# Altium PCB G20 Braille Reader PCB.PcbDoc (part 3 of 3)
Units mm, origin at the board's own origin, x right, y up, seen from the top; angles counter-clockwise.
Board outline 160.1 x 170.2 mm, 2 copper layers (Top Layer, Bottom Layer); 206 components, 272 nets, 975 pads, 345 vias.
Unrouted connection lines stored in the file: 1.
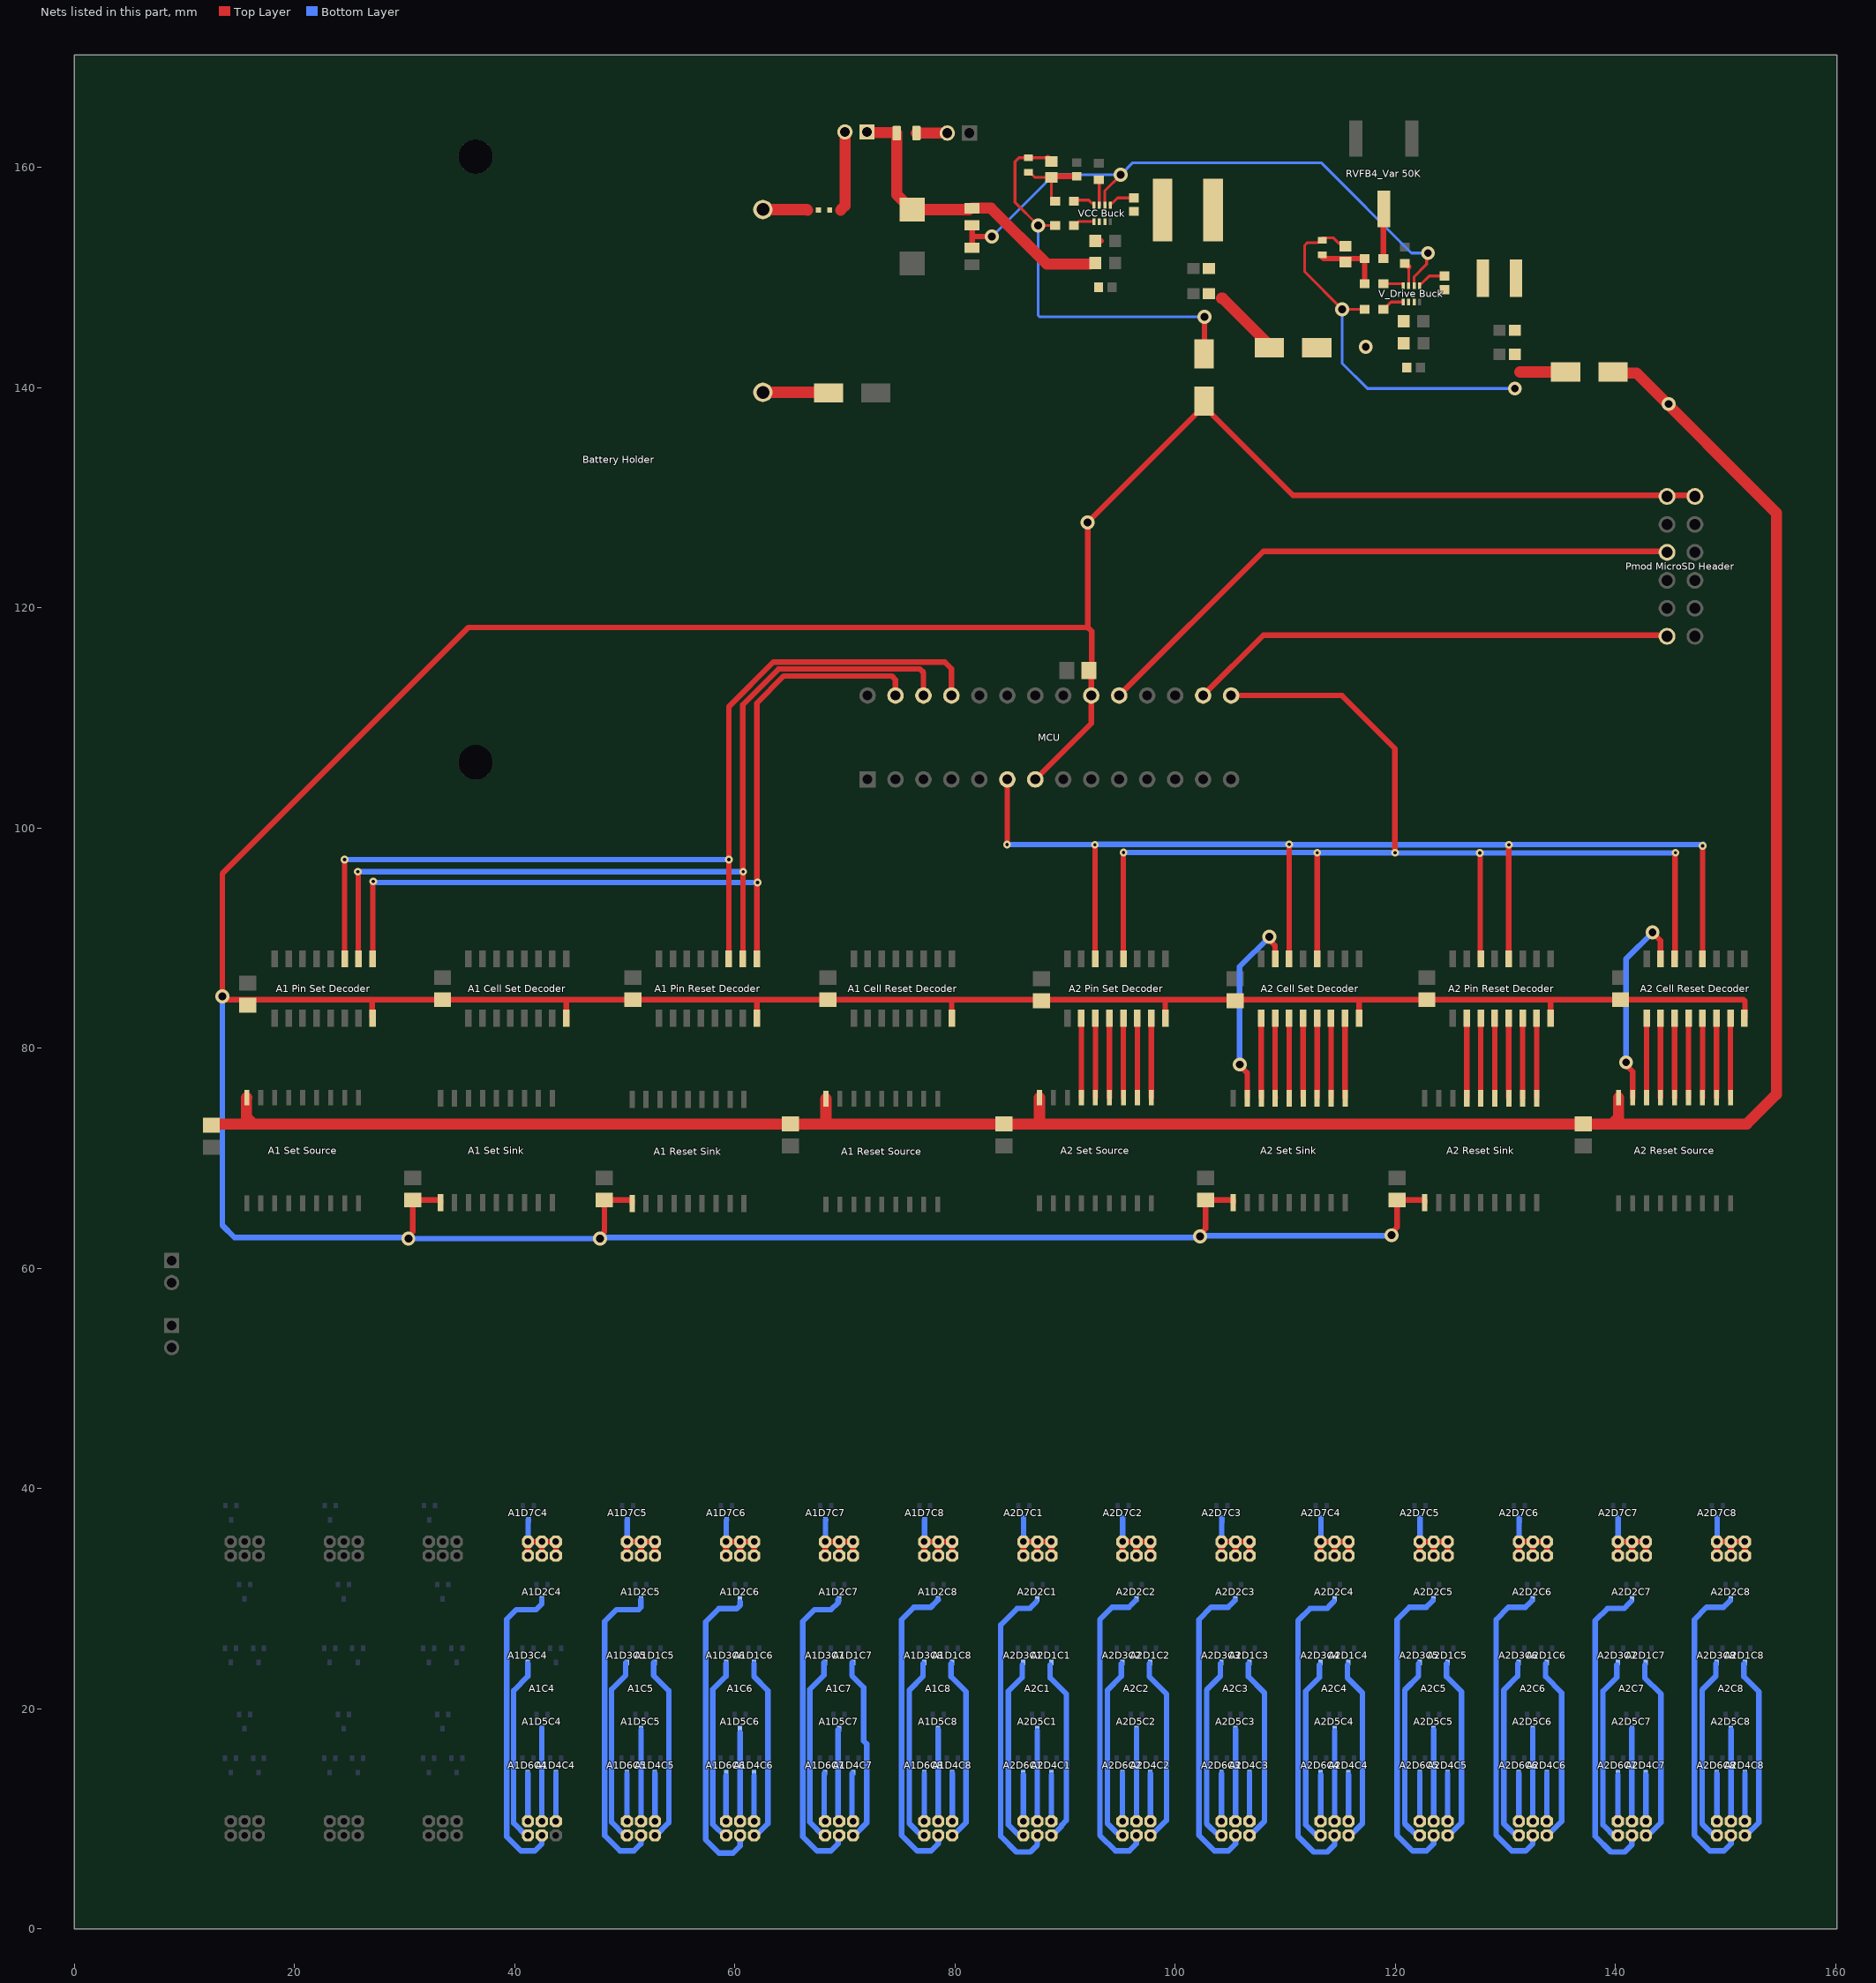
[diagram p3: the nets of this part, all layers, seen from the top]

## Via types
v1: diameter 0.7, hole 0.3, Top Layer to Bottom Layer, 308 vias
v2: diameter 1.27, hole 0.711, Top Layer to Bottom Layer, 37 vias

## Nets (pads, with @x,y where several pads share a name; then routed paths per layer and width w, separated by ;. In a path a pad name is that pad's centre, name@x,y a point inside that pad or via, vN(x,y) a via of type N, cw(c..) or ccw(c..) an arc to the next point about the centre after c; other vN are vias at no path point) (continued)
NetA1C4_P$2: A1C4.P$2 A1C4.P$4 A1C4.P$6 A1C4.P$8 A1C4.P$10 A1C4.P$12 A1D7C4.3 | length 8.4
  Top Layer w0.5: A1C4.P$8@41.2,33.907 A1C4.P$2@41.2,35.177 A1C4.P$4@42.47,35.177 ; A1C4.P$10@42.47,33.907 A1C4.P$4@42.47,35.177 ; A1C4.P$12@43.74,33.907 A1C4.P$6@43.74,35.177 A1C4.P$4@42.47,35.177
  Bottom Layer w0.5: A1C4.P$2@41.2,35.177 41.223,35.2 41.223,37.137 A1D7C4.3@41.246,37.16
NetA1C4_P$3: A1C4.P$3 A1D2C4.3 | length 28.6
  Bottom Layer w0.5: A1D2C4.3@42.467,29.906 42.457,29.896 42.457,29.516 41.946,29.005 40.146,29.005 39.273,28.132 39.273,8.386 40.56,7.099 41.83,7.099 42.47,7.739 A1C4.P$3@42.47,8.407
NetA1C4_P$5: A1C4.P$5 A1D3C4.3 | length 16.7
  Bottom Layer w0.5: A1C4.P$5@41.1,8.407 39.9,9.607 39.9,21.659 41.195,22.954 A1D3C4.3@41.195,24.097
NetA1C4_P$7: A1C4.P$7 A1D4C4.3 | length 4.4
  Bottom Layer w0.5: A1C4.P$7@43.742,9.689 A1D4C4.3@43.742,14.104
NetA1C4_P$9: A1C4.P$9 A1D5C4.3 | length 8.4
  Bottom Layer w0.5: A1C4.P$9@42.47,9.777 A1D5C4.3@42.47,18.192
NetA1C4_P$11: A1C4.P$11 A1D6C4.3 | length 4.4
  Bottom Layer w0.5: A1C4.P$11@41.202,9.689 A1D6C4.3@41.202,14.104
NetA1C5_P$1: A1C5.P$1 A1D1C5.3 | length 16.8
  Bottom Layer w0.5: A1D1C5.3@52.624,24.198 52.624,23.017 54,21.641 54,9.667 52.84,8.507 A1C5.P$1@52.74,8.507
NetA1C5_P$2: A1C5.P$2 A1C5.P$4 A1C5.P$6 A1C5.P$8 A1C5.P$10 A1C5.P$12 A1D7C5.3 | length 8.4
  Top Layer w0.5: A1C5.P$8@50.2,33.907 A1C5.P$2@50.2,35.177 A1C5.P$4@51.47,35.177 ; A1C5.P$10@51.47,33.907 A1C5.P$4@51.47,35.177 ; A1C5.P$12@52.74,33.907 A1C5.P$6@52.74,35.177 A1C5.P$4@51.47,35.177
  Bottom Layer w0.5: A1C5.P$2@50.2,35.177 50.223,35.2 50.223,37.137 A1D7C5.3@50.246,37.16
NetA1C5_P$3: A1C5.P$3 A1D2C5.3 | length 28.8
  Bottom Layer w0.5: A1D2C5.3@51.467,29.906 51.467,29.209 51.263,29.005 49.246,29.005 48.173,27.932 48.173,8.486 49.56,7.099 50.83,7.099 51.47,7.739 A1C5.P$3@51.47,8.407
NetA1C5_P$5: A1C5.P$5 A1D3C5.3 | length 16.7
  Bottom Layer w0.5: A1C5.P$5@49.989,8.508 48.8,9.698 48.8,21.771 50.084,23.055 A1D3C5.3@50.084,24.198
NetA1C5_P$7: A1C5.P$7 A1D4C5.3 | length 4.4
  Bottom Layer w0.5: A1C5.P$7@52.742,9.689 A1D4C5.3@52.742,14.104
NetA1C5_P$9: A1C5.P$9 A1D5C5.3 | length 8.4
  Bottom Layer w0.5: A1C5.P$9@51.472,9.689 A1D5C5.3@51.472,18.104
NetA1C5_P$11: A1C5.P$11 A1D6C5.3 | length 4.4
  Bottom Layer w0.5: A1C5.P$11@50.202,9.689 A1D6C5.3@50.202,14.104
NetA1C6_P$1: A1C6.P$1 A1D1C6.3 | length 16.7
  Bottom Layer w0.5: A1D1C6.3@61.735,24.097 61.735,22.916 63.007,21.644 63.007,9.584 ; A1C6.P$1@61.84,8.407 63.005,9.572
NetA1C6_P$2: A1C6.P$2 A1C6.P$4 A1C6.P$6 A1C6.P$8 A1C6.P$10 A1C6.P$12 A1D7C6.3 | length 8.4
  Top Layer w0.5: A1C6.P$8@59.2,33.907 A1C6.P$2@59.2,35.177 A1C6.P$4@60.47,35.177 ; A1C6.P$10@60.47,33.907 A1C6.P$4@60.47,35.177 ; A1C6.P$12@61.74,33.907 A1C6.P$6@61.74,35.177 A1C6.P$4@60.47,35.177
  Bottom Layer w0.5: A1C6.P$2@59.2,35.177 59.223,35.2 59.223,37.137 A1D7C6.3@59.246,37.16
NetA1C6_P$3: A1C6.P$3 A1D2C6.3 | length 28.4
  Bottom Layer w0.5: 60.467,29.706 60.467,29.393 60.174,29.1 58.541,29.1 57.346,27.905 57.346,8.113 58.56,6.899 59.83,6.899 60.47,7.539 A1C6.P$3@60.47,8.207
NetA1C6_P$5: A1C6.P$5 A1D3C6.3 | length 16.6
  Bottom Layer w0.5: A1C6.P$5@59.1,8.407 58,9.507 58,21.759 59.195,22.954 A1D3C6.3@59.195,24.097
NetA1C6_P$7: A1C6.P$7 A1D4C6.3 | length 4.4
  Bottom Layer w0.5: A1C6.P$7@61.742,9.489 61.742,13.904
NetA1C6_P$9: A1C6.P$9 A1D5C6.3 | length 8.1
  Bottom Layer w0.5: A1C6.P$9@60.47,9.777 60.47,17.836
NetA1C6_P$11: A1C6.P$11 A1D6C6.3 | length 4.4
  Bottom Layer w0.5: A1C6.P$11@59.202,9.489 59.202,13.904
NetA1C7_P$1: A1C7.P$1 A1D1C7.3 | length 16.8
  Bottom Layer w0.5: A1D1C7.3@70.624,24.198 70.624,23.017 71.7,21.941 71.7,17.079 71.973,16.806 71.973,9.64 70.84,8.507 A1C7.P$1@70.74,8.507
NetA1C7_P$2: A1C7.P$2 A1C7.P$4 A1C7.P$6 A1C7.P$8 A1C7.P$10 A1C7.P$12 A1D7C7.3 | length 8.4
  Top Layer w0.5: A1C7.P$8@68.2,33.907 A1C7.P$2@68.2,35.177 A1C7.P$4@69.47,35.177 ; A1C7.P$10@69.47,33.907 A1C7.P$4@69.47,35.177 ; A1C7.P$12@70.74,33.907 A1C7.P$6@70.74,35.177 A1C7.P$4@69.47,35.177
  Bottom Layer w0.5: A1C7.P$2@68.2,35.177 68.223,35.2 68.223,37.137 A1D7C7.3@68.246,37.16
NetA1C7_P$3: A1C7.P$3 A1D2C7.3 | length 28.4
  Bottom Layer w0.5: A1D2C7.3@69.367,29.906 69.367,29.626 68.746,29.005 67.246,29.005 66.173,27.932 66.173,8.386 67.46,7.099 68.73,7.099 69.37,7.739 A1C7.P$3@69.37,8.407
NetA1C7_P$5: A1C7.P$5 A1D3C7.3 | length 16.7
  Bottom Layer w0.5: A1C7.P$5@67.989,8.508 66.8,9.698 66.8,21.771 68.084,23.055 A1D3C7.3@68.084,24.198
NetA1C7_P$7: A1C7.P$7 A1D4C7.3 | length 4.4
  Bottom Layer w0.5: A1C7.P$7@70.642,9.689 A1D4C7.3@70.642,14.104
NetA1C7_P$9: A1C7.P$9 A1D5C7.3 | length 8.4
  Bottom Layer w0.5: A1C7.P$9@69.372,9.689 A1D5C7.3@69.372,18.104
NetA1C7_P$11: A1C7.P$11 A1D6C7.3 | length 4.4
  Bottom Layer w0.5: A1C7.P$11@68.102,9.689 A1D6C7.3@68.102,14.104
NetA1C8_P$1: A1C8.P$1 A1D1C8.3 | length 16.8
  Bottom Layer w0.5: A1D1C8.3@79.635,24.097 79.635,22.916 81,21.551 81,9.667 A1C8.P$1@79.74,8.407
NetA1C8_P$2: A1C8.P$2 A1C8.P$4 A1C8.P$6 A1C8.P$8 A1C8.P$10 A1C8.P$12 A1D7C8.3 | length 8.4
  Top Layer w0.5: A1C8.P$8@77.2,33.907 A1C8.P$2@77.2,35.177 A1C8.P$4@78.47,35.177 ; A1C8.P$10@78.47,33.907 A1C8.P$4@78.47,35.177 ; A1C8.P$12@79.74,33.907 A1C8.P$6@79.74,35.177 A1C8.P$4@78.47,35.177
  Bottom Layer w0.5: A1C8.P$2@77.2,35.177 77.223,35.2 77.223,37.137 A1D7C8.3@77.246,37.16
NetA1C8_P$3: A1C8.P$3 A1D2C8.3 | length 28.5
  Bottom Layer w0.5: A1D2C8.3@78.467,29.906 78.432,29.906 78.392,29.866 78.392,29.831 77.955,29.393 77.955,29.357 77.806,29.209 76.25,29.209 75.146,28.105 75.146,8.513 76.56,7.099 77.83,7.099 78.47,7.739 A1C8.P$3@78.47,8.407
NetA1C8_P$5: A1C8.P$5 A1D3C8.3 | length 16.7
  Bottom Layer w0.5: A1C8.P$5@77,8.407 75.846,9.561 75.846,21.705 77.095,22.954 A1D3C8.3@77.095,24.097
NetA1C8_P$7: A1C8.P$7 A1D4C8.3 | length 4.4
  Bottom Layer w0.5: A1C8.P$7@79.742,9.689 A1D4C8.3@79.742,14.104
NetA1C8_P$9: A1C8.P$9 A1D5C8.3 | length 8.4
  Bottom Layer w0.5: A1C8.P$9@78.472,9.689 A1D5C8.3@78.472,18.104
NetA1C8_P$11: A1C8.P$11 A1D6C8.3 | length 4.4
  Bottom Layer w0.5: A1C8.P$11@77.202,9.689 A1D6C8.3@77.202,14.104
"NetA2 Cell Reset Decoder_4": "A2 Cell Reset Decoder.4" "A2 Cell Set Decoder.6" "A2 Pin Reset Decoder.4" "A2 Pin Set Decoder.6" MCU.6 | length 110.4
  Top Layer w0.5: v1@84.746,98.605 MCU.6@84.746,104.405 ; v1(92.695,98.473) 92.718,98.45 92.718,88.128 92.741,88.105 ; 110.341,88.105 110.344,88.107 110.344,98.502 v1(110.346,98.505) ; 130.281,88.105 130.288,88.112 130.288,98.466 v1(130.295,98.473) ; 147.886,88.105 147.89,88.109 147.89,98.368 v1(147.895,98.373)
  Bottom Layer w0.5: v1(84.716,98.477) v1@92.695,98.477 ; v1@92.727,98.505 v1(110.346,98.505) ; v1@110.378,98.473 v1(130.295,98.473) ; v1@130.295,98.477 147.918,98.477 v1@147.946,98.505
"NetA2 Cell Reset Decoder_6": "A2 Cell Reset Decoder.6" "A2 Cell Set Decoder.4" "A2 Pin Reset Decoder.6" "A2 Pin Set Decoder.4" MCU.15 | length 115.2
  Top Layer w0.5: 95.281,88.105 95.286,88.11 95.286,97.762 v1(95.291,97.767) ; MCU.15@105.066,112.025 115.126,112.025 119.946,107.205 119.946,97.766 v1(119.967,97.746) ; 112.881,88.105 112.886,88.11 112.886,97.741 v1(112.891,97.746) ; v1(127.649,97.715) 127.695,97.669 127.695,88.151 127.741,88.105 ; 145.346,88.105 145.384,88.143 145.384,97.706 v1(145.422,97.744)
  Bottom Layer w0.5: v1@95.208,97.763 95.214,97.756 112.881,97.756 v1(112.891,97.746) ; v1@112.891,97.763 112.908,97.746 v1(119.967,97.746) ; v1@119.967,97.763 119.999,97.73 127.616,97.73 127.649,97.763 127.682,97.73 145.347,97.73 v1@145.38,97.763
"NetA2 Cell Reset Decoder_7": "A2 Cell Reset Decoder.7" "A2 Reset Source.8" | length 18.9
  Top Layer w0.5: v2(140.946,78.705) 140.946,78.448 141.536,77.858 141.536,75.505 ; v2(143.346,90.505) 144.076,89.775 144.076,88.105
  Bottom Layer w0.5: v2(140.946,78.705) 140.946,88.105 v2(143.346,90.505)
"NetA2 Cell Reset Decoder_9": "A2 Cell Reset Decoder.9" "A2 Reset Source.7" | length 7.2
  Top Layer w0.5: 142.806,75.505 142.806,82.705
"NetA2 Cell Reset Decoder_10": "A2 Cell Reset Decoder.10" "A2 Reset Source.6" | length 7.2
  Top Layer w0.5: 144.076,75.505 144.076,82.705
"NetA2 Cell Reset Decoder_11": "A2 Cell Reset Decoder.11" "A2 Reset Source.5" | length 7.2
  Top Layer w0.5: 145.346,75.505 145.346,82.705
"NetA2 Cell Reset Decoder_12": "A2 Cell Reset Decoder.12" "A2 Reset Source.4" | length 7.2
  Top Layer w0.5: 146.616,75.505 146.616,82.705
"NetA2 Cell Reset Decoder_13": "A2 Cell Reset Decoder.13" "A2 Reset Source.3" | length 7.2
  Top Layer w0.5: 147.886,75.505 147.886,82.705
"NetA2 Cell Reset Decoder_14": "A2 Cell Reset Decoder.14" "A2 Reset Source.2" | length 7.2
  Top Layer w0.5: 149.156,75.505 149.156,82.705
"NetA2 Cell Reset Decoder_15": "A2 Cell Reset Decoder.15" "A2 Reset Source.1" | length 7.2
  Top Layer w0.5: 150.426,75.505 150.426,82.705
"NetA2 Cell Set Decoder_7": "A2 Cell Set Decoder.7" "A2 Set Sink.8" | length 18.2
  Top Layer w0.5: v2(105.846,78.505) 105.846,78.448 106.536,77.758 106.536,75.505 ; v2(108.546,90.105) 108.546,89.83 109.071,89.305 109.071,88.105
  Bottom Layer w0.5: v2(105.846,78.505) 105.846,87.405 v2(108.546,90.105)
"NetA2 Cell Set Decoder_9": "A2 Cell Set Decoder.9" "A2 Set Sink.7" | length 7.2
  Top Layer w0.5: 107.801,82.705 107.804,82.702 107.804,75.507 107.806,75.505
"NetA2 Cell Set Decoder_10": "A2 Cell Set Decoder.10" "A2 Set Sink.6" | length 7.2
  Top Layer w0.5: 109.071,82.705 109.074,82.702 109.074,75.507 109.076,75.505
"NetA2 Cell Set Decoder_11": "A2 Cell Set Decoder.11" "A2 Set Sink.5" | length 7.2
  Top Layer w0.5: 110.341,82.705 110.344,82.702 110.344,75.507 110.346,75.505
"NetA2 Cell Set Decoder_12": "A2 Cell Set Decoder.12" "A2 Set Sink.4" | length 7.2
  Top Layer w0.5: 111.611,82.705 111.614,82.702 111.614,75.507 111.616,75.505
"NetA2 Cell Set Decoder_13": "A2 Cell Set Decoder.13" "A2 Set Sink.3" | length 7.2
  Top Layer w0.5: 112.881,82.705 112.884,82.702 112.884,75.507 112.886,75.505
"NetA2 Cell Set Decoder_14": "A2 Cell Set Decoder.14" "A2 Set Sink.2" | length 7.2
  Top Layer w0.5: 114.151,82.705 114.154,82.702 114.154,75.507 114.156,75.505
"NetA2 Cell Set Decoder_15": "A2 Cell Set Decoder.15" "A2 Set Sink.1" | length 7.2
  Top Layer w0.5: 115.421,82.705 115.424,82.702 115.424,75.507 115.426,75.505
"NetA2 Pin Reset Decoder_10": "A2 Pin Reset Decoder.10" "A2 Reset Sink.6" | length 7.2
  Top Layer w0.5: 126.471,82.705 126.474,82.702 126.474,75.507 126.476,75.505
"NetA2 Pin Reset Decoder_11": "A2 Pin Reset Decoder.11" "A2 Reset Sink.5" | length 7.2
  Top Layer w0.5: 127.741,82.705 127.744,82.702 127.744,75.507 127.746,75.505
"NetA2 Pin Reset Decoder_12": "A2 Pin Reset Decoder.12" "A2 Reset Sink.4" | length 7.2
  Top Layer w0.5: 129.011,82.705 129.014,82.702 129.014,75.507 129.016,75.505
"NetA2 Pin Reset Decoder_13": "A2 Pin Reset Decoder.13" "A2 Reset Sink.3" | length 7.2
  Top Layer w0.5: 130.281,82.705 130.284,82.702 130.284,75.507 130.286,75.505
"NetA2 Pin Reset Decoder_14": "A2 Pin Reset Decoder.14" "A2 Reset Sink.2" | length 7.2
  Top Layer w0.5: 131.551,82.705 131.554,82.702 131.554,75.507 131.556,75.505
"NetA2 Pin Reset Decoder_15": "A2 Pin Reset Decoder.15" "A2 Reset Sink.1" | length 7.2
  Top Layer w0.5: 132.821,82.705 132.824,82.702 132.824,75.507 132.826,75.505
"NetA2 Pin Set Decoder_10": "A2 Pin Set Decoder.10" "A2 Set Source.6" | length 7.2
  Top Layer w0.5: 91.471,82.705 91.474,82.702 91.474,75.507 91.476,75.505
"NetA2 Pin Set Decoder_11": "A2 Pin Set Decoder.11" "A2 Set Source.5" | length 7.2
  Top Layer w0.5: 92.741,82.705 92.744,82.702 92.744,75.507 92.746,75.505
"NetA2 Pin Set Decoder_12": "A2 Pin Set Decoder.12" "A2 Set Source.4" | length 7.2
  Top Layer w0.5: 94.011,82.705 94.014,82.702 94.014,75.507 94.016,75.505
"NetA2 Pin Set Decoder_13": "A2 Pin Set Decoder.13" "A2 Set Source.3" | length 7.2
  Top Layer w0.5: 95.281,82.705 95.284,82.702 95.284,75.507 95.286,75.505
"NetA2 Pin Set Decoder_14": "A2 Pin Set Decoder.14" "A2 Set Source.2" | length 7.2
  Top Layer w0.5: 96.551,82.705 96.554,82.702 96.554,75.507 96.556,75.505
"NetA2 Pin Set Decoder_15": "A2 Pin Set Decoder.15" "A2 Set Source.1" | length 7.2
  Top Layer w0.5: 97.821,82.705 97.824,82.702 97.824,75.507 97.826,75.505
NetA2C1_P$1: A2C1.P$1 A2D1C1.3 | length 16.7
  Bottom Layer w0.5: A2D1C1.3@88.635,23.997 88.635,22.816 90.1,21.351 90.1,9.867 89.671,9.438 89.671,9.344 88.834,8.507 A2C1.P$1@88.74,8.507
NetA2C1_P$2: A2C1.P$2 A2C1.P$4 A2C1.P$6 A2C1.P$8 A2C1.P$10 A2C1.P$12 A2D7C1.3 | length 8.3
  Top Layer w0.5: A2C1.P$8@86.2,33.907 A2C1.P$2@86.2,35.177 A2C1.P$4@87.47,35.177 ; A2C1.P$10@87.47,33.907 A2C1.P$4@87.47,35.177 ; A2C1.P$12@88.74,33.907 A2C1.P$6@88.74,35.177 A2C1.P$4@87.47,35.177
  Bottom Layer w0.5: A2C1.P$2@86.223,35.4 A2D7C1.3@86.223,37.337
NetA2C1_P$3: A2C1.P$3 A2D2C1.3 | length 27.9
  Bottom Layer w0.5: 86.806,29.109 85.64,29.109 84.146,27.615 84.146,8.413 85.56,6.999 86.83,6.999 87.47,7.639 A2C1.P$3@87.47,8.307 ; 86.955,29.293 87.392,29.731
NetA2C1_P$5: A2C1.P$5 A2D3C1.3 | length 16.7
  Bottom Layer w0.5: A2C1.P$5@86,8.307 84.846,9.461 84.846,21.605 86.095,22.854 A2D3C1.3@86.095,23.997
NetA2C1_P$7: A2C1.P$7 A2D4C1.3 | length 4.4
  Bottom Layer w0.5: A2C1.P$7@88.742,9.589 A2D4C1.3@88.742,14.004
NetA2C1_P$9: A2C1.P$9 A2D5C1.3 | length 8.4
  Bottom Layer w0.5: A2C1.P$9@87.472,9.589 A2D5C1.3@87.472,18.004
NetA2C1_P$11: A2C1.P$11 A2D6C1.3 | length 4.4
  Bottom Layer w0.5: A2C1.P$11@86.202,9.589 A2D6C1.3@86.202,14.004
NetA2C2_P$1: A2C2.P$1 A2D1C2.3 | length 16.9
  Bottom Layer w0.5: A2D1C2.3@97.635,24.097 97.635,22.916 99.2,21.351 99.2,9.867 A2C2.P$1@97.74,8.407
NetA2C2_P$2: A2C2.P$2 A2C2.P$4 A2C2.P$6 A2C2.P$8 A2C2.P$10 A2C2.P$12 A2D7C2.3 | length 8.3
  Top Layer w0.5: A2C2.P$8@95.2,33.907 A2C2.P$2@95.2,35.177 A2C2.P$4@96.47,35.177 ; A2C2.P$10@96.47,33.907 A2C2.P$4@96.47,35.177 ; A2C2.P$12@97.74,33.907 A2C2.P$6@97.74,35.177 A2C2.P$4@96.47,35.177
  Bottom Layer w0.5: A2C2.P$2@95.223,35.4 A2D7C2.3@95.223,37.337
NetA2C2_P$3: A2C2.P$3 A2D2C2.3 | length 28.2
  Bottom Layer w0.5: 95.806,29.209 94.25,29.209 93.146,28.105 93.146,8.513 94.56,7.099 95.83,7.099 96.47,7.739 A2C2.P$3@96.47,8.407 ; 95.955,29.393 A2D2C2.3@96.392,29.831
NetA2C2_P$5: A2C2.P$5 A2D3C2.3 | length 16.7
  Bottom Layer w0.5: A2C2.P$5@95,8.407 93.846,9.561 93.846,21.705 95.095,22.954 A2D3C2.3@95.095,24.097
NetA2C2_P$7: A2C2.P$7 A2D4C2.3 | length 4.4
  Bottom Layer w0.5: A2C2.P$7@97.742,9.689 A2D4C2.3@97.742,14.104
NetA2C2_P$9: A2C2.P$9 A2D5C2.3 | length 8.4
  Bottom Layer w0.5: A2C2.P$9@96.472,9.689 A2D5C2.3@96.472,18.104
NetA2C2_P$11: A2C2.P$11 A2D6C2.3 | length 4.4
  Bottom Layer w0.5: A2C2.P$11@95.202,9.689 A2D6C2.3@95.202,14.104
NetA2C3_P$1: A2C3.P$1 A2D1C3.3 | length 16.9
  Bottom Layer w0.5: A2D1C3.3@106.635,24.097 106.635,22.916 108.1,21.451 108.1,9.767 A2C3.P$1@106.74,8.407
NetA2C3_P$2: A2C3.P$2 A2C3.P$4 A2C3.P$6 A2C3.P$8 A2C3.P$10 A2C3.P$12 A2D7C3.3 | length 8.3
  Top Layer w0.5: A2C3.P$8@104.2,33.907 A2C3.P$2@104.2,35.177 A2C3.P$4@105.47,35.177 ; A2C3.P$10@105.47,33.907 A2C3.P$4@105.47,35.177 ; A2C3.P$12@106.74,33.907 A2C3.P$6@106.74,35.177 A2C3.P$4@105.47,35.177
  Bottom Layer w0.5: A2C3.P$2@104.223,35.4 A2D7C3.3@104.223,37.337
NetA2C3_P$3: A2C3.P$3 A2D2C3.3 | length 28.2
  Bottom Layer w0.5: 104.806,29.209 103.25,29.209 102.146,28.105 102.146,8.513 103.56,7.099 104.83,7.099 105.47,7.739 A2C3.P$3@105.47,8.407 ; 104.955,29.393 A2D2C3.3@105.392,29.831
NetA2C3_P$5: A2C3.P$5 A2D3C3.3 | length 16.7
  Bottom Layer w0.5: A2C3.P$5@104,8.407 102.846,9.561 102.846,21.705 104.095,22.954 A2D3C3.3@104.095,24.097
NetA2C3_P$7: A2C3.P$7 A2D4C3.3 | length 4.4
  Bottom Layer w0.5: A2C3.P$7@106.742,9.689 A2D4C3.3@106.742,14.104
NetA2C3_P$9: A2C3.P$9 A2D5C3.3 | length 8.4
  Bottom Layer w0.5: A2C3.P$9@105.472,9.689 A2D5C3.3@105.472,18.104
NetA2C3_P$11: A2C3.P$11 A2D6C3.3 | length 4.4
  Bottom Layer w0.5: A2C3.P$11@104.202,9.689 A2D6C3.3@104.202,14.104
NetA2C4_P$1: A2C4.P$1 A2D1C4.3 | length 16.8
  Bottom Layer w0.5: A2D1C4.3@115.635,23.997 115.635,22.816 117,21.451 117,9.567 A2C4.P$1@115.74,8.307
NetA2C4_P$2: A2C4.P$2 A2C4.P$4 A2C4.P$6 A2C4.P$8 A2C4.P$10 A2C4.P$12 A2D7C4.3 | length 8.3
  Top Layer w0.5: A2C4.P$8@113.2,33.907 A2C4.P$2@113.2,35.177 A2C4.P$4@114.47,35.177 ; A2C4.P$10@114.47,33.907 A2C4.P$4@114.47,35.177 ; A2C4.P$12@115.74,33.907 A2C4.P$6@115.74,35.177 A2C4.P$4@114.47,35.177
  Bottom Layer w0.5: A2C4.P$2@113.223,35.4 A2D7C4.3@113.223,37.337
NetA2C4_P$3: A2C4.P$3 A2D2C4.3 | length 28.2
  Bottom Layer w0.5: 113.806,29.109 112.25,29.109 111.146,28.005 111.146,8.413 112.56,6.999 113.83,6.999 114.47,7.639 A2C4.P$3@114.47,8.307 ; 113.955,29.293 114.392,29.731
NetA2C4_P$5: A2C4.P$5 A2D3C4.3 | length 16.7
  Bottom Layer w0.5: A2C4.P$5@113,8.307 111.846,9.461 111.846,21.605 113.095,22.854 A2D3C4.3@113.095,23.997
NetA2C4_P$7: A2C4.P$7 A2D4C4.3 | length 4.4
  Bottom Layer w0.5: A2C4.P$7@115.742,9.589 A2D4C4.3@115.742,14.004
NetA2C4_P$9: A2C4.P$9 A2D5C4.3 | length 8.4
  Bottom Layer w0.5: A2C4.P$9@114.472,9.589 A2D5C4.3@114.472,18.004
NetA2C4_P$11: A2C4.P$11 A2D6C4.3 | length 4.4
  Bottom Layer w0.5: A2C4.P$11@113.202,9.589 A2D6C4.3@113.202,14.004
NetA2C5_P$1: A2C5.P$1 A2D1C5.3 | length 16.8
  Bottom Layer w0.5: A2D1C5.3@124.635,24.097 124.635,22.916 126,21.551 126,9.667 A2C5.P$1@124.74,8.407
NetA2C5_P$2: A2C5.P$2 A2C5.P$4 A2C5.P$6 A2C5.P$8 A2C5.P$10 A2C5.P$12 A2D7C5.3 | length 8.3
  Top Layer w0.5: A2C5.P$8@122.2,33.907 A2C5.P$2@122.2,35.177 A2C5.P$4@123.47,35.177 ; A2C5.P$10@123.47,33.907 A2C5.P$4@123.47,35.177 ; A2C5.P$12@124.74,33.907 A2C5.P$6@124.74,35.177 A2C5.P$4@123.47,35.177
  Bottom Layer w0.5: A2C5.P$2@122.223,35.4 A2D7C5.3@122.223,37.337
NetA2C5_P$3: A2C5.P$3 A2D2C5.3 | length 28.2
  Bottom Layer w0.5: 122.806,29.209 121.25,29.209 120.146,28.105 120.146,8.513 121.56,7.099 122.83,7.099 123.47,7.739 A2C5.P$3@123.47,8.407 ; 122.955,29.393 A2D2C5.3@123.392,29.831
NetA2C5_P$5: A2C5.P$5 A2D3C5.3 | length 16.7
  Bottom Layer w0.5: A2C5.P$5@122,8.407 120.846,9.561 120.846,21.705 122.095,22.954 A2D3C5.3@122.095,24.097
NetA2C5_P$7: A2C5.P$7 A2D4C5.3 | length 4.4
  Bottom Layer w0.5: A2C5.P$7@124.742,9.689 A2D4C5.3@124.742,14.104
NetA2C5_P$9: A2C5.P$9 A2D5C5.3 | length 8.4
  Bottom Layer w0.5: A2C5.P$9@123.472,9.689 A2D5C5.3@123.472,18.104
NetA2C5_P$11: A2C5.P$11 A2D6C5.3 | length 4.4
  Bottom Layer w0.5: A2C5.P$11@122.202,9.689 A2D6C5.3@122.202,14.104
NetA2C6_P$1: A2C6.P$1 A2D1C6.3 | length 16.9
  Bottom Layer w0.5: A2D1C6.3@133.635,24.097 133.635,22.916 135.1,21.451 135.1,9.767 A2C6.P$1@133.74,8.407
NetA2C6_P$2: A2C6.P$2 A2C6.P$4 A2C6.P$6 A2C6.P$8 A2C6.P$10 A2C6.P$12 A2D7C6.3 | length 8.3
  Top Layer w0.5: A2C6.P$8@131.2,33.907 A2C6.P$2@131.2,35.177 A2C6.P$4@132.47,35.177 ; A2C6.P$10@132.47,33.907 A2C6.P$4@132.47,35.177 ; A2C6.P$12@133.74,33.907 A2C6.P$6@133.74,35.177 A2C6.P$4@132.47,35.177
  Bottom Layer w0.5: A2C6.P$2@131.223,35.4 A2D7C6.3@131.223,37.337
NetA2C6_P$3: A2C6.P$3 A2D2C6.3 | length 28.2
  Bottom Layer w0.5: 131.806,29.209 130.25,29.209 129.146,28.105 129.146,8.513 130.56,7.099 131.83,7.099 132.47,7.739 A2C6.P$3@132.47,8.407 ; 131.955,29.393 A2D2C6.3@132.392,29.831
NetA2C6_P$5: A2C6.P$5 A2D3C6.3 | length 16.7
  Bottom Layer w0.5: A2C6.P$5@131,8.407 129.846,9.561 129.846,21.705 131.095,22.954 A2D3C6.3@131.095,24.097
NetA2C6_P$7: A2C6.P$7 A2D4C6.3 | length 4.4
  Bottom Layer w0.5: A2C6.P$7@133.742,9.689 A2D4C6.3@133.742,14.104
NetA2C6_P$9: A2C6.P$9 A2D5C6.3 | length 8.4
  Bottom Layer w0.5: A2C6.P$9@132.472,9.689 A2D5C6.3@132.472,18.104
NetA2C6_P$11: A2C6.P$11 A2D6C6.3 | length 4.4
  Bottom Layer w0.5: A2C6.P$11@131.202,9.689 A2D6C6.3@131.202,14.104
NetA2C7_P$1: A2C7.P$1 A2D1C7.3 | length 16.9
  Bottom Layer w0.5: A2D1C7.3@142.635,23.997 142.635,22.816 144.1,21.351 144.1,9.667 A2C7.P$1@142.74,8.307
NetA2C7_P$2: A2C7.P$2 A2C7.P$4 A2C7.P$6 A2C7.P$8 A2C7.P$10 A2C7.P$12 A2D7C7.3 | length 8.3
  Top Layer w0.5: A2C7.P$8@140.2,33.907 A2C7.P$2@140.2,35.177 A2C7.P$4@141.47,35.177 ; A2C7.P$10@141.47,33.907 A2C7.P$4@141.47,35.177 ; A2C7.P$12@142.74,33.907 A2C7.P$6@142.74,35.177 A2C7.P$4@141.47,35.177
  Bottom Layer w0.5: A2C7.P$2@140.223,35.4 A2D7C7.3@140.223,37.337
NetA2C7_P$3: A2C7.P$3 A2D2C7.3 | length 28.2
  Bottom Layer w0.5: 140.806,29.109 139.25,29.109 138.146,28.005 138.146,8.413 139.56,6.999 140.83,6.999 141.47,7.639 A2C7.P$3@141.47,8.307 ; 140.955,29.293 141.392,29.731
NetA2C7_P$5: A2C7.P$5 A2D3C7.3 | length 16.7
  Bottom Layer w0.5: A2C7.P$5@140,8.307 138.846,9.461 138.846,21.605 140.095,22.854 A2D3C7.3@140.095,23.997
NetA2C7_P$7: A2C7.P$7 A2D4C7.3 | length 4.4
  Bottom Layer w0.5: A2C7.P$7@142.742,9.589 A2D4C7.3@142.742,14.004
NetA2C7_P$9: A2C7.P$9 A2D5C7.3 | length 8.4
  Bottom Layer w0.5: A2C7.P$9@141.47,9.777 A2D5C7.3@141.47,18.192
NetA2C7_P$11: A2C7.P$11 A2D6C7.3 | length 4.4
  Bottom Layer w0.5: A2C7.P$11@140.202,9.589 A2D6C7.3@140.202,14.004
NetA2C8_P$1: A2C8.P$1 A2D1C8.3 | length 16.8
  Bottom Layer w0.5: A2D1C8.3@151.635,24.097 151.635,22.916 153,21.551 153,9.667 A2C8.P$1@151.74,8.407
NetA2C8_P$2: A2C8.P$2 A2C8.P$4 A2C8.P$6 A2C8.P$8 A2C8.P$10 A2C8.P$12 A2D7C8.3 | length 8.3
  Top Layer w0.5: A2C8.P$8@149.2,33.907 A2C8.P$2@149.2,35.177 A2C8.P$4@150.47,35.177 ; A2C8.P$10@150.47,33.907 A2C8.P$4@150.47,35.177 ; A2C8.P$12@151.74,33.907 151.746,33.907 151.74,33.913 A2C8.P$6@151.74,35.177 A2C8.P$4@150.47,35.177
  Bottom Layer w0.5: A2C8.P$2@149.223,35.4 A2D7C8.3@149.223,37.337
NetA2C8_P$3: A2C8.P$3 A2D2C8.3 | length 28.2
  Bottom Layer w0.5: 149.806,29.209 148.25,29.209 147.146,28.105 147.146,8.513 148.56,7.099 149.83,7.099 150.47,7.739 A2C8.P$3@150.47,8.407 ; 149.955,29.393 A2D2C8.3@150.392,29.831
NetA2C8_P$5: A2C8.P$5 A2D3C8.3 | length 16.7
  Bottom Layer w0.5: A2C8.P$5@149,8.407 147.846,9.561 147.846,21.705 149.095,22.954 A2D3C8.3@149.095,24.097
NetA2C8_P$7: A2C8.P$7 A2D4C8.3 | length 4.4
  Bottom Layer w0.5: A2C8.P$7@151.742,9.689 A2D4C8.3@151.742,14.104
NetA2C8_P$9: A2C8.P$9 A2D5C8.3 | length 8.4
  Bottom Layer w0.5: A2C8.P$9@150.472,9.689 A2D5C8.3@150.472,18.104
NetA2C8_P$11: A2C8.P$11 A2D6C8.3 | length 4.4
  Bottom Layer w0.5: A2C8.P$11@149.202,9.689 A2D6C8.3@149.202,14.104
NetBT_NEG: "Battery Holder.NEG" SKD.2 | length 6
  Top Layer w0.5: SKD.2@68.446,139.555 SKD.2@68.496,139.505
  Top Layer w1.016: 62.546,139.555 SKD.2@68.446,139.555
NetBT_POS: "Battery Holder.POS" Fuse1.1 | length 4.1
  Top Layer w1.016: 62.546,156.155 66.545,156.155 66.6,156.1
NetCBST1_1: "VCC Buck.5" CBST1.1 | length 2.5
  Top Layer w0.254: 94.096,156.552 94.096,156.716 94.109,156.729 94.272,156.729 94.762,157.218 CBST1.1@96.246,157.218
NetCBST2_1: "V_Drive Buck.5" CBST2.1 | length 2.7
  Top Layer w0.254: 122.196,149.252 122.196,149.416 122.209,149.429 122.372,149.429 123.062,150.118 CBST2.1@124.446,150.118
NetCFF1_1: CFF1.1 RFB1.1 RFB2.2 RT1.2 | length 7
  Top Layer w0.254: RFB1.1@86.746,159.555 87.221,159.08 CFF1.1@88.746,159.08 88.746,157.205 RT1.2@89.046,156.905
  Top Layer w0.5: RFB1.1@86.646,159.555 RFB1.1@86.746,159.555 ; CFF1.1@88.746,159.08 88.844,159.178 RFB2.2@91.046,159.178 ; RT1.2@89.046,156.905 RT1.2@89.096,156.905
NetCFF2_1: "RFB4_Fixed 10K.2" CFF2.1 RFB3.1 RT2.2 | length 6.2
  Top Layer w0.5: RFB3.1@113.346,151.83 113.471,151.705 115.446,151.705 117.196,151.705 RT2.2@117.196,149.405
NetCSS1_1: "VCC Buck.7" CSS1.1 | length 2.3
  Top Layer w0.254: 93.096,156.552 CSS1.1@93.096,158.805
  Top Layer w0.5: CSS1.1@93.046,158.855 CSS1.1@93.096,158.805
NetCSS2_1: "V_Drive Buck.7" CSS2.1 | length 2.2
  Top Layer w0.254: 121.196,149.252 CSS2.1@121.196,150.955
  Top Layer w0.5: CSS2.1@120.846,151.255 120.896,151.255 CSS2.1@121.196,150.955
NetFuse1_2: "Power Switch.2" Fuse1.2 | length 7.3
  Top Layer w1.016: 69.6,156.1 70,156.5 70,163.2
NetLED_2: LED.2 R_LED.2 | length 2.8
  Top Layer w1.016: R_LED.2@76.49,163.1 LED.2@79.3,163.1
"NetRFB4_Fixed 10K_1": "RFB4_Fixed 10K.1" "RVFB4_Var 50K.2" | length 4.5
  Top Layer w0.5: 118.896,151.705 118.896,156.155 118.946,156.205
"Pin Select 0": "A1 Pin Reset Decoder.1" "A1 Pin Set Decoder.1" MCU.27 | length 80.4
  Top Layer w0.5: 27.091,88.105 27.12,88.134 27.12,95.101 v1(27.149,95.129) ; 61.991,88.105 61.991,95.029 61.991,111.331 64.46,113.8 74.239,113.8 74.586,113.453 MCU.27@74.586,112.025
  Bottom Layer w0.5: v1@27.121,95.029 v1(62.049,95.029)
"Pin Select 1": "A1 Pin Reset Decoder.2" "A1 Pin Set Decoder.2" MCU.26 | length 85.9
  Top Layer w0.5: v1(25.749,96.029) 25.785,95.993 25.785,88.141 25.821,88.105 ; 60.721,88.105 60.735,88.119 60.735,96.016 60.721,96.029 60.721,111.18 63.968,114.427 76.811,114.427 77.126,114.112 MCU.26@77.126,112.025
  Bottom Layer w0.5: v1@25.846,96.005 25.871,96.029 v1(60.749,96.029)
"Pin Select 2": "A1 Pin Reset Decoder.3" "A1 Pin Set Decoder.3" MCU.25 | length 91.3
  Top Layer w0.5: v1(24.549,97.129) 24.55,97.128 24.55,88.106 24.551,88.105 ; 59.451,88.105 59.45,88.106 59.45,97.128 59.451,97.129 59.451,111.01 63.495,115.054 79.068,115.054 79.666,114.456 MCU.25@79.666,112.025
  Bottom Layer w0.5: v1@24.621,97.129 v1(59.449,97.129)
SCK: "Pmod MicroSD Header.4" MCU.19 | length 54.8
  Top Layer w0.508: MCU.19@94.906,112.025 108.006,125.125 144.306,125.125
V_Drive: "A1 Reset Source.9" "A1 Set Source.9" "A2 Reset Source.9" "A2 Set Source.9" C5_D.2 C8_D.2 C13_D.2 C16_D.2 SKD2.2 | length 226.4
  Top Layer w1.016: C5_D.2@12.446,73.005 12.546,73.105 16.241,73.105 ; 15.666,75.505 15.646,75.485 15.646,73.7 16.241,73.105 ; 68.266,75.405 68.266,73.125 68.246,73.105 ; 87.666,75.505 87.666,73.125 87.646,73.105 ; SKD2.2@139.65,141.4 139.737,141.313 141.887,141.313 154.6,128.6 154.6,75.8 151.905,73.105 139.671,73.105 ; 140.266,75.505 140.266,73.7 139.671,73.105 ; 16.241,73.105 C8_D.2@65.046,73.105 68.246,73.105 ; 68.246,73.105 C13_D.2@84.446,73.105 87.646,73.105 ; 87.646,73.105 C16_D.2@137.046,73.105 139.671,73.105
  other v2: 144.8,138.5
V_Drive1: CFF2.2 Cout3.1 Cout4.1 L2.2 RFB3.2 RPG2.1 SKD2.1 | length 39.4
  Top Layer w0.254: CFF2.2@115.446,152.505 114.371,153.58 113.346,153.58 112.898,153.132 111.973,153.132 111.746,152.905 111.746,150.505 v2(115.146,147.105) RPG2.1@117.196,147.105
  Top Layer w1.016: 131.3,141.4 SKD2.1@135.45,141.4
  Bottom Layer w0.254: v2(115.146,147.105) 115.146,142.205 117.446,139.905 v2(130.846,139.905)
VCC: "A1 Cell Reset Decoder.16" "A1 Cell Set Decoder.16" "A1 Pin Reset Decoder.16" "A1 Pin Set Decoder.16" "A1 Reset Sink.10" "A1 Set Sink.10" "A2 Cell Reset Decoder.16" "A2 Cell Set Decoder.16" "A2 Pin Reset Decoder.16" "A2 Pin Set Decoder.16" "A2 Reset Sink.10" "A2 Set Sink.10" "Pmod MicroSD Header.6" "Pmod MicroSD Header.12" C1_D.1 C1_MCU.2 C2_D.1 C3_D.1 C4_D.1 C6_D.2 C7_D.2 C9_D.1 C10_D.1 C11_D.1 C12_D.1 C14_D.2 C15_D.2 MCU.7 MCU.20 SKD1.2 | length 492.6
  Top Layer w0.5: MCU.20@92.366,112.025 MCU.20@92.383,112.042 ; C1_MCU.2@92.383,113.888 C1_MCU.2@92.4,113.905
  Top Layer w0.508: C1_D.1@15.946,84.405 13.744,84.405 v2(13.446,84.702) 13.446,95.846 35.805,118.205 92.046,118.205 ; C1_D.1@16.146,84.405 27.046,84.405 ; 27.091,82.705 27.046,82.75 27.046,84.405 ; v2(30.346,62.705) 30.346,62.911 30.746,63.311 C6_D.2@30.746,66.205 33.255,66.205 33.266,66.194 33.266,65.967 ; 44.691,82.705 44.691,84.256 44.542,84.405 ; v2(47.746,62.705) 47.746,62.911 48.146,63.311 C7_D.2@48.146,66.205 50.655,66.205 50.666,66.194 50.666,65.867 ; 61.991,82.705 61.991,84.26 61.846,84.405 ; 79.691,82.705 79.691,84.36 79.646,84.405 ; MCU.7@87.286,104.405 92.366,109.485 MCU.20@92.366,112.025 ; MCU.20@92.383,112.042 C1_MCU.2@92.383,113.888 ; C1_MCU.2@92.4,113.905 92.4,117.85 92.046,118.205 ; 99.091,82.705 99.091,84.36 99.046,84.405 ; v2(102.246,62.905) 102.246,63.111 102.746,63.611 C14_D.2@102.746,66.205 105.255,66.205 105.266,66.194 105.266,65.967 ; SKD1.2@102.6,138.75 SKD1.2@102.6,138.3 ; 116.691,82.705 116.691,84.36 116.646,84.405 ; v2(119.646,63.005) 119.646,63.211 120.146,63.711 C15_D.2@120.146,66.205 122.655,66.205 122.666,66.194 122.666,65.967 ; 134.091,82.705 134.091,84.35 134.146,84.405 ; 146.846,130.205 144.306,130.205 110.695,130.205 SKD1.2@102.6,138.3 ; 151.696,82.705 151.746,82.755 151.746,84.256 151.597,84.405 134.146,84.405 ; 27.046,84.405 44.542,84.405 ; 44.542,84.405 61.846,84.405 ; 61.846,84.405 79.646,84.405 ; 79.646,84.405 99.046,84.405 ; 92.046,118.205 v2(92.046,127.746) SKD1.2@102.6,138.3 ; 99.046,84.405 116.646,84.405 ; 116.646,84.405 134.146,84.405
  Bottom Layer w0.508: v2(13.446,84.702) 13.446,63.905 14.546,62.805 30.246,62.805 v2(30.346,62.705) v2(47.746,62.705) 47.846,62.805 102.146,62.805 102.346,63.005 102.396,62.955 119.596,62.955 v2(119.646,63.005)
VCC1: CFF1.2 Cout1.1 Cout2.1 L1.2 RFB1.2 RPG1.1 SKD1.1 SKDB.1 | length 45.3
  Top Layer w0.254: CFF1.2@88.421,160.855 RFB1.2@86.646,160.855 85.796,160.855 85.446,160.505 85.446,156.805 v2(87.546,154.705) RPG1.1@89.096,154.705
  Top Layer w0.5: CFF1.2@88.421,160.855 CFF1.2@88.746,160.53
  Top Layer w0.508: SKD1.1@102.6,143.05 102.646,143.096 v2(102.646,146.405)
  Top Layer w1.016: 104.2,148.1 104.3,148.1 108.7,143.7 SKDB.1@109.15,143.7
  Bottom Layer w0.254: v2(87.546,154.705) 87.546,146.554 87.695,146.405 v2(102.646,146.405)
VCC_Filtered: "V_Drive Buck.2" Cin4.2 Cin5.2 Cin6.1 SKDB.2
  other v2: 117.3,143.7
VEN_Buck: "V_Drive Buck.6" "VCC Buck.6" RDown_EN.2 Rup_EN.1 | length 56.4
  Top Layer w0.254: 93.596,156.552 93.596,157.855 v2(95.046,159.305) ; 121.696,149.252 121.696,150.055 122.83,151.189 v2@122.83,152.089
  Top Layer w0.5: RDown_EN.2@81.546,152.68 81.546,153.705 ; Rup_EN.1@81.546,154.73 81.546,153.705 ; v2(83.346,153.705) 81.546,153.705 ; v2@122.83,152.089 v2(122.946,152.205)
  Bottom Layer w0.254: v2(83.346,153.705) 88.946,159.305 v2(95.046,159.305) 96.146,160.405 113.246,160.405 121.446,152.205 v2(122.946,152.205)
VFB1: "VCC Buck.8" RT1.1 | length 2
  Top Layer w0.254: RT1.1@90.796,157.005 92.144,157.005 92.596,156.552
VFB2: "V_Drive Buck.8" RT2.1 | length 1.9
  Top Layer w0.254: RT2.1@118.896,149.405 120.683,149.405 120.696,149.392 120.696,149.252
Vin: "Power Switch.1" "VCC Buck.2" Cin1.2 Cin2.2 Cin3.1 R_LED.1 Rup_EN.2 TVS.2 | length 28.5
  Top Layer w0.5: Cin1.2@93.109,153.442 Cin1.2@93.246,153.305
  Top Layer w1.016: 72,163.2 72.05,163.15 74.65,163.15 R_LED.1@74.7,163.1 74.7,157.5 76.05,156.15 TVS.2@76.1,156.15 81.282,156.15 Rup_EN.2@81.3,156.168 ; Rup_EN.2@81.546,156.28 83.271,156.28 88.346,151.205 Cin2.2@92.246,151.205
VPG1: "VCC Buck.1" RPG1.2 | length 1.9
  Top Layer w0.254: RPG1.2@90.846,154.705 91.198,155.057 92.596,155.057
  Top Layer w0.5: RPG1.2@90.796,154.705 RPG1.2@90.846,154.705
VPG2: "V_Drive Buck.1" RPG2.2 | length 2.1
  Top Layer w0.254: RPG2.2@118.946,147.105 119.598,147.757 120.696,147.757
  Top Layer w0.5: RPG2.2@118.896,147.105 RPG2.2@118.946,147.105
VSW1: "VCC Buck.3" CBST1.2 L1.1
VSW2: "V_Drive Buck.3" CBST2.2 L2.1
~CS: "Pmod MicroSD Header.1" MCU.16 | length 44
  Top Layer w0.508: MCU.16@102.526,112.025 108.006,117.505 144.306,117.505
pads on no net: "A1 Pin Reset Decoder.7" "A1 Pin Reset Decoder.9" "A1 Pin Set Decoder.7" "A1 Pin Set Decoder.9" "A1 Reset Sink.7" "A1 Reset Sink.8" "A1 Reset Sink.11" "A1 Reset Sink.12" "A1 Set Source.7" "A1 Set Source.8" "A1 Set Source.11" "A1 Set Source.12" "A2 Pin Reset Decoder.7" "A2 Pin Reset Decoder.9" "A2 Pin Set Decoder.7" "A2 Pin Set Decoder.9" "A2 Reset Sink.7" "A2 Reset Sink.8" "A2 Reset Sink.11" "A2 Reset Sink.12" "A2 Set Source.7" "A2 Set Source.8" "A2 Set Source.11" "A2 Set Source.12" "Battery Holder." "Pmod MicroSD Header.7" "Pmod MicroSD Header.8" "Pmod MicroSD Header.10" "RVFB4_Var 50K.1"

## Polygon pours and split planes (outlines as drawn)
GND on Top Layer "GND_L01_P020" (solid, remove dead copper, pour order 20): 0.6,169.4 159.4,169.4 159.4,0.6 0.6,0.6
NetFuse1_2 on Top Layer "NETFUSE1_2_L01_P027" (solid, remove dead copper, pour order 27): 68.4,155.6 68.4,156.6 69.6,156.6 69.6,155.6
NetBT_POS on Top Layer "NETBT_POS_L01_P028" (solid, remove dead copper, pour order 28): 67.8,156.6 67.8,155.6 66.6,155.6 66.6,156.6
VCC_Filtered on Top Layer "VCC_FILTERED_L01_P026" (solid, remove dead copper, pour order 26): 112.3,142.8 112.3,144.4 115.7,144.4 116.4,145.1 119.6,145.1 119.6,145.951 119.546,146.005 120.946,147.405 121.046,147.405 121.046,148.105 121.346,148.105 121.346,147.505 121.546,147.305 121.546,140.705 119.546,140.705 119.546,142.054 119.5,142.1 116.5,142.1 115.8,142.8
V_Drive on Top Layer "V_DRIVE_L01_P022" (solid, remove dead copper, pour order 22): 143.7,136.4 142.1,138 142.1,140.5 142.8,141.2 145.2,141.2 146.9,139.5 146.9,137 146.7,137 146.1,136.4 146.7,137 146.1,136.4
V_Drive1 on Top Layer "V_DRIVE1_L01_P013" (solid, pour order 13): 130.346,151.705 130.346,139.705 131.646,139.705 132.196,140.355 132.146,150.505 131.646,151.705
GND on Top Layer "GND_L01_P006" (solid, pour order 6): 93.946,155.405 94.246,155.405 97.846,151.805 102.146,151.805 102.146,147.505 93.746,147.505 93.746,154.505 93.946,154.705
VSW2 on Top Layer "VSW2_L01_P012" (solid, pour order 12): 121.846,147.405 121.546,147.405 121.546,148.505 121.746,148.705 122.446,148.705 123.146,149.405 125.346,149.405 126.146,149.505 127.136,151.705 128.546,151.705 128.546,147.905 123.246,147.905 122.746,148.405 122.046,148.405 121.846,148.205
GND on Top Layer "GND_L01_P011" (solid, pour order 11): 122.046,148.105 122.046,147.205 121.746,146.905 121.746,140.705 129.846,140.705 129.846,145.905 124.546,145.905 122.346,148.105
VSW1 on Top Layer "VSW1_L01_P005" (solid, pour order 5): 93.446,154.705 93.446,155.705 93.746,156.005 94.246,156.005 94.646,156.405 96.946,156.405 97.346,156.805 97.729,159.005 100.046,159.005 100.046,153.205 97.526,153.205 95.246,155.105 94.846,155.105 94.246,155.705 93.946,155.705 93.746,155.505 93.746,154.705
Vin on Top Layer "VIN_L01_P002" (solid, pour order 2): 93.246,154.705 93.546,154.405 93.546,147.505 91.446,147.505 91.446,153.205 92.946,154.705
VCC1 on Top Layer "VCC1_L01_P009" (solid, pour order 9): 102.446,146.005 102.446,159.005 104.548,159.005 104.846,146.005
GND on Top Layer "GND_L01_P014" (solid, pour order 14): 120.146,152.305 121.746,152.305 121.746,159.43 117.389,164.44 117.346,164.505 117.246,164.605 115.246,164.605 115.246,160.705 115.446,160.505 118.046,160.505 120.046,158.505
Vin on Top Layer "VIN_L01_P001" (solid, pour order 1): 92.946,155.405 93.246,155.405 93.246,154.205 92.946,154.205
GND on Bottom Layer "GND_L02_P019" (solid, remove dead copper, pour order 19): 159.4,169.4 159.4,0.6 0.6,0.6 0.6,169.4
VCC_Filtered on Bottom Layer "VCC_FILTERED_L02_P025" (solid, remove dead copper, pour order 25): 116.5,142.1 115.8,142.8 115.8,144.3 115.7,144.4 116.4,145.1 119.5,145.1 119.5,142.1
V_Drive on Bottom Layer "V_DRIVE_L02_P023" (solid, remove dead copper, pour order 23): 143.7,136.4 142.1,138 142.1,140.4 142.8,141.1 142.8,141.2 145.2,141.2 146.9,139.5 146.9,137 146.3,136.4 146.1,136.4

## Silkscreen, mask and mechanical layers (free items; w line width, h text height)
Top Overlay:
  text "GND Test Point" at 7.454,165.754 h1.52
  text "GND Test Point" at 135.654,161.854 h1.52
  text "hack the planet" at 9.254,161.487 h1
  text "V_Drive" at 146.254,144.308 h1.52
  text "Refreshable" at 25.6,141.959 h1.52
  text "Test Point" at 144.454,141.654 h1.52
  text "Group 20" at 11.054,140.362 h1.52
  text "Braille Display" at 24.1,138.867 h1.52
  text "Buck" at 114.554,137.254 h1.52
  text "Albert Li, Evan Hartnell" at 25.673,136.786 h0.76
  text "Ashley Cheung, Miles Taylor" at 25.727,135.181 h0.76
  text "Test Point" at 110.454,135.054 h1.52
  text "VCC Test Point" at 69.954,127.154 h1.52
  text "SCK" at 137.44,125.854 h1
  text "MISO" at 136.607,123.244 h1
  text "MOSI" at 136.773,120.644 h1
  text "CS" at 138.439,118.144 h1
  text "CD" at 149.154,113.154 h1
  text "Pin Set" at 13.754,91.954 h1
  text "Cell Set" at 31.254,91.954 h1
  text "Pin Reset" at 48.554,91.954 h1
  text "Cell Reset" at 66.154,91.954 h1
  text "Source" at 18.254,62.254 h1
  text "Sink" at 36.654,62.254 h1
  text "Sink" at 54.154,62.254 h1
  text "Source" at 70.854,62.254 h1
  text "5" at 15.554,11.254 h0.5
  text "1" at 12.654,10.654 h0.5
  text "4" at 18.154,10.654 h0.5
  text "6" at 18.354,7.154 h0.5
  text "3" at 12.654,6.854 h0.5
  text "2" at 15.454,6.454 h0.5
  text "GND Test Point" at 132.654,4.554 h1.52
  text "GND Test Point" at 9.354,3.854 h1.52
Top Designator:
Top 3D Body:
  text "This is our refreshable braile display PCB" at 3.054,151.862 h1.52
  text "This is our designed PCB for the" at 9.654,149.362 h1.52
  text "refreshable braille display project" at 10.554,146.262 h1.52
